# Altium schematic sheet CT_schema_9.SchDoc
size 251 x 159 mm
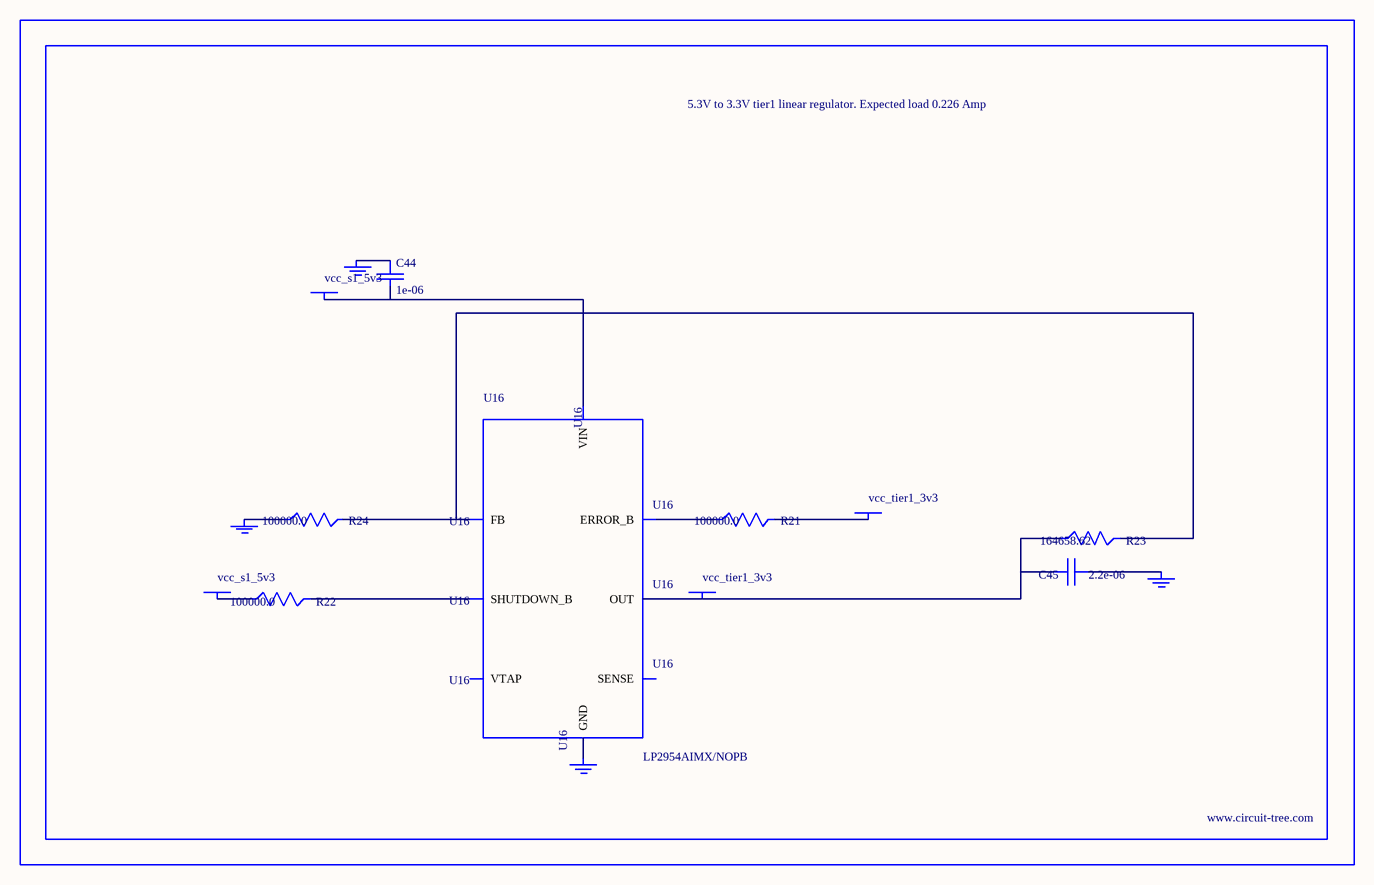
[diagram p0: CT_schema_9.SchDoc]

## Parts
BORDER8  (no value)
C44  1e-06  [EXV-9B]
C45  2.2e-06  [EXV-9B]
GND_INSTANCE_8_0  (no value)
GND_INSTANCE_8_1  (no value)
GND_INSTANCE_8_2  (no value)
GND_INSTANCE_8_3  (no value)
POWER_INSTANCE_8_0  vcc_s1_5v3
POWER_INSTANCE_8_1  vcc_tier1_3v3
POWER_INSTANCE_8_2  vcc_s1_5v3
POWER_INSTANCE_8_3  vcc_tier1_3v3
R21  100000.0  [R0603]
R22  100000.0  [R0603]
R23  164658.62  [R0603]
R24  100000.0  [R0603]
U16  LP2954AIMX/NOPB  [LP2954]

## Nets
NetC44_1: C44.1 GND_INSTANCE_8_2.0(GND)
NetC44_2: C44.2 POWER_INSTANCE_8_2.0(PWR) U16.8(VIN)
NetC45_1: C45.1 GND_INSTANCE_8_0.0(GND)
NetC45_2: C45.2 POWER_INSTANCE_8_3.0(PWR) R23.1 U16.1(OUT)
NetGND_INSTANCE_8_1_0: GND_INSTANCE_8_1.0(GND) R24.1
NetGND_INSTANCE_8_3_0: GND_INSTANCE_8_3.0(GND) U16.4(GND)
NetPOWER_INSTANCE_8_0_0: POWER_INSTANCE_8_0.0(PWR) R22.1
NetPOWER_INSTANCE_8_1_0: POWER_INSTANCE_8_1.0(PWR) R21.2
NetR21_1: R21.1 U16.5(ERROR_B)
NetR22_2: R22.2 U16.3(SHUTDOWN_B)
NetR23_2: R23.2 R24.2 U16.7(FB)

Not connected (* = marked no-connect by the designer): U16 2(SENSE) 6(VTAP)

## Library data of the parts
BORDER8 = BORDER_PAGE8
C44 = EDK105M050A9BAA
C45 = EDK225M050A9BAA
GND_INSTANCE_8_0-GND_INSTANCE_8_3 = GND
POWER_INSTANCE_8_0-POWER_INSTANCE_8_3 = PWR
R21 R22 R24 = RC0603JR-07100KL
R23 = R23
